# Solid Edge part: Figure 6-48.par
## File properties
Author: Ashutosh-CADCIM
Template: Iso Metric Part.par
Last saved by: Ashutosh-CADCIM
Revision: 2
Application: Solid Edge
Accuracy: 0.990
Username: Ashutosh-CADCIM
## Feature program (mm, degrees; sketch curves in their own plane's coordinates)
sketch for "unnamed Protrusion 1" plane through (0, 0, 0) normal (0, 0, 1) x-axis (1, 0, 0)
  line (-100, -100) -> (100, -100)
  line (100, -100) -> (100, 100)
  line (100, 100) -> (-100, 100)
  line (-100, 100) -> (-100, -100)
extrude "unnamed Protrusion 1" add finite 20 symmetric
sketch for "ExtrudedCutout_1" plane through (0, 0, 10) normal (0, 0, 1) x-axis (1, 0, 0)
  circle centre (80, -80) radius 10
  dimension (linear) = 80
extrude "ExtrudedCutout_1" cut finite 81.8886 along -normal
pattern "unnamed Pattern 1" of "ExtrudedCutout_1"
extrude "unnamed Cutout 1" cut finite 81.8886
extrude "unnamed Cutout 2" cut finite 81.8886
extrude "unnamed Cutout 3" cut finite 81.8886
extrude "unnamed Cutout 4" cut finite 81.8886
extrude "unnamed Cutout 5" cut finite 81.8886
extrude "unnamed Cutout 6" cut finite 81.8886
extrude "unnamed Cutout 7" cut finite 81.8886
extrude "unnamed Cutout 8" cut finite 81.8886
extrude "unnamed Cutout 9" cut finite 81.8886
extrude "unnamed Cutout 10" cut finite 81.8886
extrude "unnamed Cutout 11" cut finite 81.8886
extrude "unnamed Cutout 12" cut finite 81.8886
extrude "unnamed Cutout 13" cut finite 81.8886
extrude "unnamed Cutout 14" cut finite 81.8886
extrude "unnamed Cutout 15" cut finite 81.8886
extrude "unnamed Cutout 16" cut finite 81.8886
extrude "unnamed Cutout 17" cut finite 81.8886
extrude "unnamed Cutout 18" cut finite 81.8886
extrude "unnamed Cutout 19" cut finite 81.8886
extrude "unnamed Cutout 20" cut finite 81.8886
extrude "unnamed Cutout 21" cut finite 81.8886
extrude "unnamed Cutout 22" cut finite 81.8886
extrude "unnamed Cutout 23" cut finite 81.8886
extrude "unnamed Cutout 24" cut finite 81.8886
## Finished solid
Body 1: solid body, 33 faces, 70 edges, 16 vertices.
  Faces by surface: cylinder 25, plane 8
  Edges by curve: circle 50, line 20
Bounding box of the edges (mm): 200.000 x 200.000 x 20.000, from (-100, -100, -10) to (100, 100, 10).
Cylindrical faces by radius (mm): R10 x25
Planar faces by outward normal: +x 1, +y 3, +z 1, -x 1, -y 1, -z 1
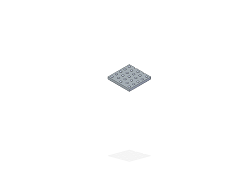
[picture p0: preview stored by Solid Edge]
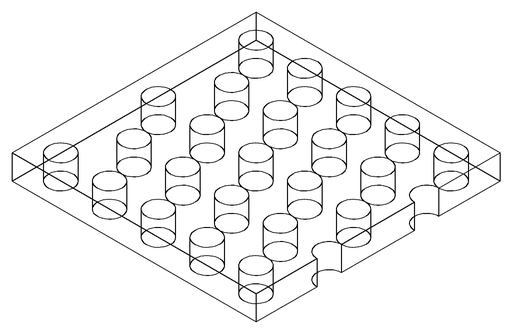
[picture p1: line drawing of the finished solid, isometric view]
